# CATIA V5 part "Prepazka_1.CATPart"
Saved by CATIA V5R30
Part number: Prepazka_1
Definition: E 21000_12_125__l_cut_to_length_90_1
Nomenclature: E 21000_12_125__l_cut_to_length_90_1
Source: Unknown
Description: PART-E 21000_12_125__l_cut_to_length_90_1-DESC
Bounding box of the stored display mesh (mm): x -6 to 6, y -6 to 6, z 0 to 98
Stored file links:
  E:\Bakalarka\Model\Forma_v7\Prepazka_1.CATPart
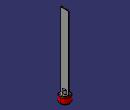
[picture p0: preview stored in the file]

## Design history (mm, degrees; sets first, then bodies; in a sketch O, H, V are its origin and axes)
Body1 "E 21000_12_125__l_cut_to_length_90" (main body)
  Solid1: solid without history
